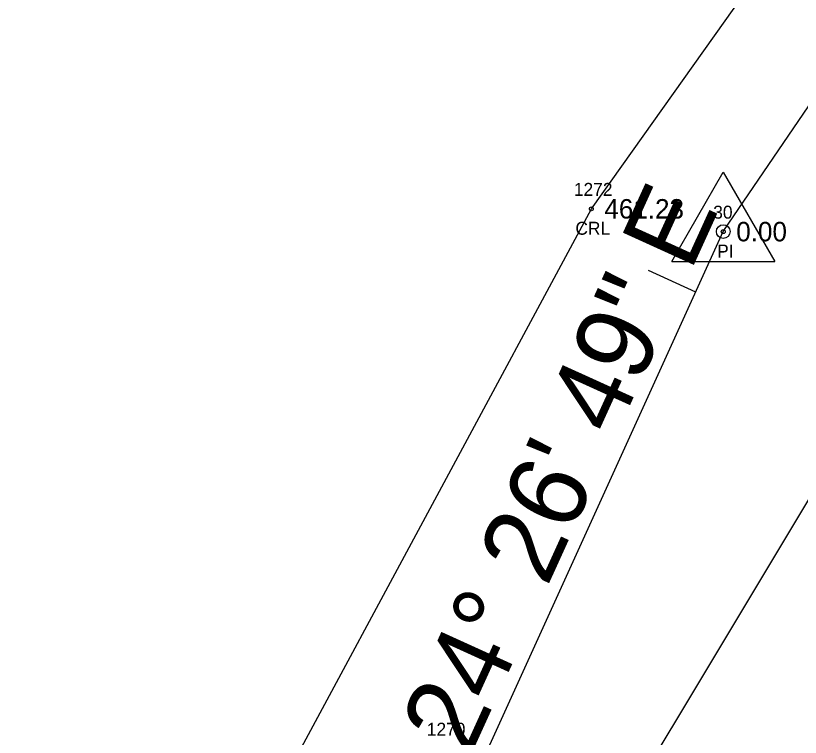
# Model space of a CAD drawing. Extents: x 1784103 to 1787401, y 770251 to 771298.
# Drawn here: x 1785796.9 to 1785857.4, y 770937.5 to 770993.2 of the extents above; entities that cross this region are included whole.
import ezdxf

# ---------------------------------------------------------------- set-up
doc = ezdxf.new("R2010")
doc.units = 0
for name, color, linetype in [('RD_EX_H2O', 7, 'Continuous'), ('RD_EX_H2O_txCode', 7, 'Continuous'), ('RD_EX_TX_H2O_ELEV', 7, 'Continuous'), ('RD_HC_Cl', 7, 'Continuous'), ('RD_HC_Data', 7, 'Continuous'), ('RD_HC_Data_Tic', 7, 'Continuous'), ('RD_HC_Survey_ELEV', 7, 'Continuous'), ('RD_HC_txCode', 7, 'Continuous'), ('RD_SMD_Locator', 7, 'Continuous')]:
    doc.layers.add(name, color=color, linetype=linetype)

msp = doc.modelspace()

# ---------------------------------------------------------------- linework, layer by layer
at = {"layer": 'RD_EX_H2O'}
for points in [[(1785796.945, 770894.214), (1785817.521, 770934.075), (1785841.283, 770978.267), (1785905.839, 771069.133), (1785934.056, 771107.398), (1785932.736, 771138.873), (1785957.105, 771183.158), (1785993.968, 771208.538), (1785990.477, 771236.162), (1786004.551, 771296.266)], [(1785823.912, 770890.023), (1785840.027, 770925.863), (1785869.787, 770975.477), (1785920.387, 771060.625), (1785947.122, 771092.256), (1785958.507, 771131.143), (1785974.055, 771169.928), (1786009.635, 771197.712), (1786027.988, 771233.036), (1786021.728, 771286.51)]]:
    msp.add_lwpolyline(points, dxfattribs=at)
at = {"layer": 'RD_HC_Cl'}
for p, q in [((1785851.444, 770976.509), (1785912.041, 771065.72)), ((1785830.731, 770930.948), (1785851.444, 770976.509))]:
    msp.add_line(p, q, dxfattribs=at)
at = {"layer": 'RD_HC_Data'}
for p, q in [((1785847.473, 770974.217), (1785851.445, 770981.096)), ((1785851.445, 770981.096), (1785855.414, 770974.217)), ((1785847.473, 770974.217), (1785855.414, 770974.217))]:
    msp.add_line(p, q, dxfattribs=at)
msp.add_circle((1785851.444, 770976.509), 0.529, dxfattribs=at)
at = {"layer": 'RD_HC_Data_Tic'}
msp.add_line((1785849.323, 770971.846), (1785845.682, 770973.501), dxfattribs=at)
at = {"layer": 'RD_SMD_Locator'}
for centre in [(1785841.283, 770978.267), (1785851.444, 770976.509)]:
    msp.add_circle(centre, 0.15, dxfattribs=at)

# ---------------------------------------------------------------- texts
at = {"layer": 'RD_EX_H2O_txCode'}
for s, p in [('1272', (1785839.936, 770979.267)), ('CRL', (1785840.054, 770976.267)), ('1270', (1785828.609, 770937.659))]:
    msp.add_text(s, height=1, dxfattribs=at).set_placement(p)
at = {"layer": 'RD_EX_TX_H2O_ELEV'}
msp.add_text('461.23', height=1.5, dxfattribs=at).set_placement((1785842.283, 770977.517))
at = {"layer": 'RD_HC_Data'}
msp.add_text('N 24%%d 26\' 49" E', height=6, rotation=65.55304, dxfattribs=at).set_placement((1785828.598, 770928.672))
at = {"layer": 'RD_HC_Survey_ELEV'}
msp.add_text('0.00', height=1.5, dxfattribs=at).set_placement((1785852.444, 770975.759))
at = {"layer": 'RD_HC_txCode'}
for s, p in [('30', (1785850.672, 770977.509)), ('PI', (1785850.971, 770974.509))]:
    msp.add_text(s, height=1, dxfattribs=at).set_placement(p)

doc.saveas('drawing.dxf')
